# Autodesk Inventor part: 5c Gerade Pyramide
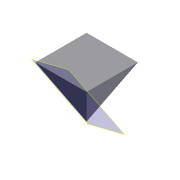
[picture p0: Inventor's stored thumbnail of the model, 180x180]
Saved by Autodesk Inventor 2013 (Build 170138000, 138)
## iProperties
Created: 2012-10
Part Number: 5c Gerade Pyramide
Material: Allgemein
Vendor: www.inventor-faq.de
Document SubType Name: Modeling
Designer: Administrator
Manufacturer: www.inventor-faq.de
Density: 1 g/cm^3
RuleStatus: InUse
AfterDocOpen0: inventorfaq
BeforeDocSave0: inventorfaq
Author: Administrator
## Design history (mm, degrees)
sketch "Skizze1"
  geometry: L1 (-5, -5)-(5, -5); L2 (5, -5)-(5, 5); L3 (5, 5)-(-5, 5); L4 (-5, 5)-(-5, -5); L5 (-5, -5)-(5, 5); L6 (5, -5)-(-5, 5); 1 further point
  constraints: 12 end point, 2 midpoint, 2 parallel, 1 horizontal, 1 perpendicular
  dimensions: "d0" = 10 distance of L3.end L2.end; "d1" = 10 distance of L2.end L1.end
extrude "Extrusion1" new body sketch "Skizze1" distance "d2" = 10; taper "d3" = 0 deg
workplane "Arbeitsebene2"
sketch "Skizze3"
  geometry: L1 (-2.041, 4.564)-(8.165, 9.129) reference; L2 (8.165, 9.129)-(12.247, 0) reference; L3 (12.247, 0)-(2.041, -4.564) reference; L4 (2.041, -4.564)-(-2.041, 4.564) reference; 1 further point
extrude "Extrusion3" cut sketch "Skizze3" stored distance "d6" = 10; taper "d7" = 0 deg
pattern_circular "Runde Anordnung1" dims angle "d9" = 360 deg
node "Volumenkörper1"
node "Schnittkanten projizieren2"
